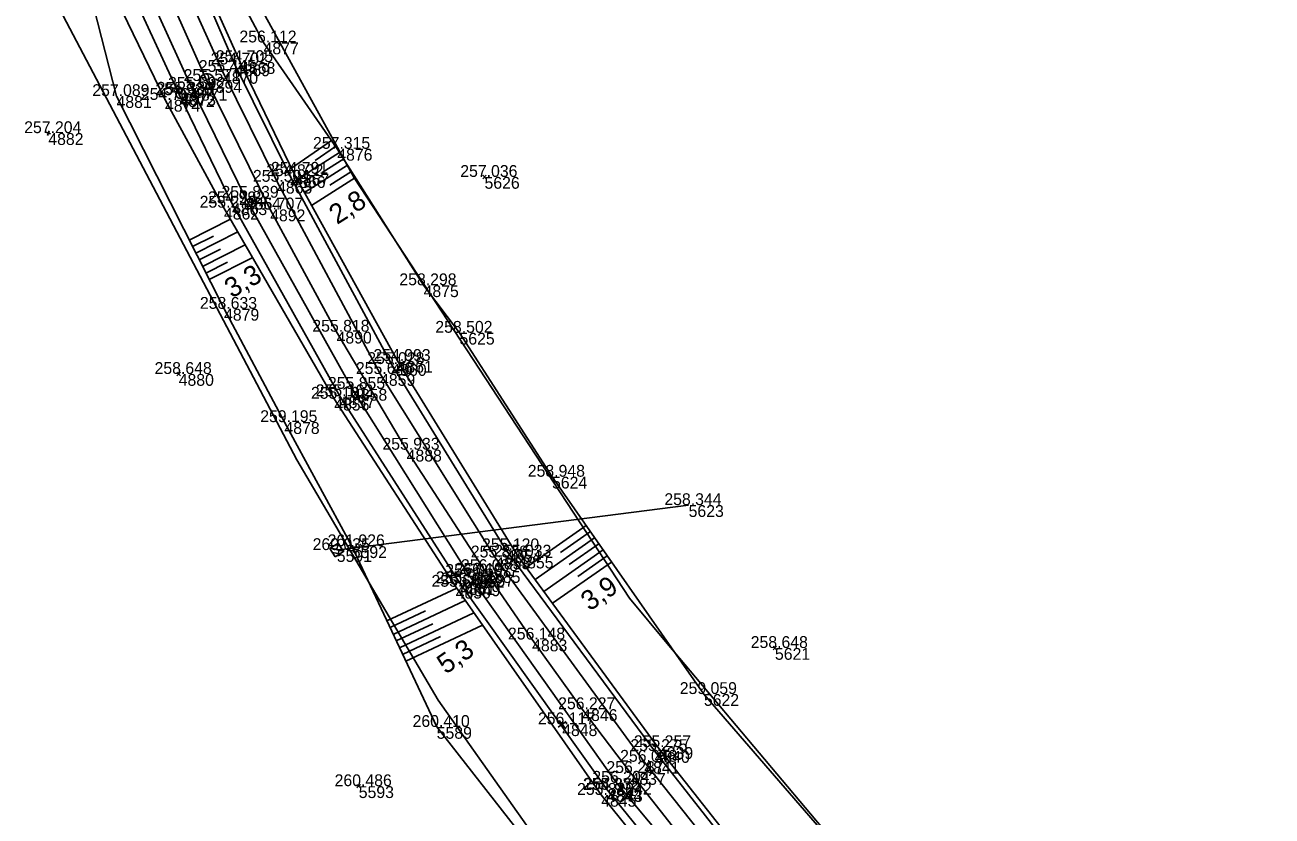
# Model space of a CAD drawing. Extents: x -809970 to -809480, y -1011362 to -1010672.
# Drawn here: x -809838.5 to -809711.9, y -1011112.9 to -1011032.7 of the extents above; entities that cross this region are included whole.
import ezdxf

# ---------------------------------------------------------------- set-up
doc = ezdxf.new("R2010")
doc.units = 0
for name, color, linetype in [('Vrstva 1', 7, 'Continuous'), ('Vrstva 25', 7, 'Continuous'), ('Vrstva 36', 7, 'Continuous'), ('Vrstva 4', 7, 'Continuous'), ('Vrstva 48', 7, 'Continuous'), ('Vrstva 49', 7, 'Continuous'), ('Vrstva 53', 7, 'Continuous'), ('Vrstva 60', 7, 'Continuous'), ('Vrstva 61', 7, 'Continuous'), ('Vrstva 7', 7, 'Continuous')]:
    doc.layers.add(name, color=color, linetype=linetype)

msp = doc.modelspace()

# ---------------------------------------------------------------- linework, layer by layer
at = {"layer": 'Vrstva 1'}
msp.add_lwpolyline([(-809704.48, -1011179.77), (-809716.3, -1011170.61), (-809726.57, -1011161.99), (-809737.88, -1011151.76), (-809747.09, -1011142.76), (-809755.44, -1011134.04), (-809764.34, -1011124.1), (-809767.12, -1011120.83), (-809771.86, -1011115.08), (-809777.01, -1011108.56), (-809781.91, -1011102.09), (-809787, -1011095.02), (-809791.76, -1011088.08), (-809799.73, -1011075.77), (-809806.84, -1011063.8), (-809813.58, -1011051.4), (-809820, -1011038.37), (-809825.44, -1011026.1)], dxfattribs=at)
at = {"layer": 'Vrstva 25'}
msp.add_lwpolyline([(-809806.82, -1011085.95), (-809771.12, -1011081.39)], dxfattribs=at)
at = {"layer": 'Vrstva 36'}
for p, q in [((-809806.19, -1011086), (-809807.41, -1011085.74)), ((-809806.51, -1011086.34), (-809807.26, -1011086.18)), ((-809806.5, -1011085.53), (-809806.94, -1011085.43))]:
    msp.add_line(p, q, dxfattribs=at)
msp.add_lwpolyline([(-809806.97, -1011086.64), (-809807.51, -1011085.8), (-809806.67, -1011085.26), (-809806.13, -1011086.1), (-809806.97, -1011086.64)], dxfattribs=at)
at = {"layer": 'Vrstva 4'}
for points in [[(-809514.07, -1011276.67), (-809539.83, -1011264.26), (-809562.29, -1011253.6), (-809585.06, -1011242.59), (-809604.03, -1011233.74), (-809622.75, -1011224.34), (-809635.98, -1011217.78), (-809658.04, -1011205.96), (-809678.21, -1011194.44), (-809694.3, -1011183.84), (-809703.86, -1011176.66), (-809724.9, -1011159.78), (-809744.11, -1011141.6), (-809762.15, -1011122.16), (-809774.57, -1011106.33), (-809789.63, -1011085.97), (-809801.28, -1011067.08), (-809811.54, -1011048.02), (-809817.16, -1011036.69), (-809823.08, -1011022.98)], [(-809514.73, -1011277.55), (-809539.87, -1011265.31), (-809562.72, -1011254.42), (-809585.31, -1011243.69), (-809604.51, -1011234.26), (-809623.3, -1011225.16), (-809636.52, -1011218.94), (-809659.57, -1011206.8), (-809678.11, -1011195.78), (-809694.14, -1011185.08), (-809704.56, -1011177.6), (-809725.72, -1011160.53), (-809745.22, -1011142.43), (-809763.07, -1011123.23), (-809775.62, -1011107.42), (-809790.76, -1011086.7), (-809802.43, -1011068.09), (-809812.88, -1011048.59), (-809818.37, -1011037.45), (-809824.5, -1011023.86)], [(-809517.34, -1011281.17), (-809542.25, -1011268.91), (-809565.05, -1011257.74), (-809585.85, -1011248.03), (-809606.19, -1011237.96), (-809624.44, -1011229.46), (-809639.03, -1011221.78), (-809662.37, -1011209.59), (-809679.75, -1011199.24), (-809695.35, -1011189.16), (-809706.37, -1011181.63), (-809728.71, -1011163.52), (-809748.04, -1011145.82), (-809766.46, -1011126.18), (-809779.35, -1011110.29), (-809779.4, -1011110.26), (-809794.33, -1011089.31), (-809806.51, -1011070.34), (-809817.46, -1011050.77), (-809822.78, -1011039.81), (-809827.65, -1011029.26)], [(-809516.72, -1011279.86), (-809541.72, -1011267.84), (-809564.36, -1011257.13), (-809585.64, -1011247.05), (-809605.96, -1011237.21), (-809624.35, -1011228.4), (-809638.66, -1011221.38), (-809661.97, -1011208.93), (-809679.17, -1011198.73), (-809694.94, -1011188.71), (-809705.67, -1011180.87), (-809727.9, -1011162.91), (-809747.29, -1011144.85), (-809765.46, -1011125.12), (-809778.44, -1011109.55), (-809793.36, -1011088.57), (-809805.27, -1011069.6), (-809816.07, -1011050.21), (-809821.49, -1011039.16), (-809826.21, -1011028.82)]]:
    msp.add_lwpolyline(points, dxfattribs=at)
at = {"layer": 'Vrstva 48'}
for p, q in [((-809807.36, -1011044.39), (-809811.42, -1011047.21)), ((-809806.53, -1011045.64), (-809810.83, -1011048.36)), ((-809806.94, -1011045.01), (-809809.01, -1011046.45)), ((-809805.72, -1011046.9), (-809810.1, -1011049.67)), ((-809806.12, -1011046.27), (-809808.29, -1011047.64)), ((-809804.92, -1011048.17), (-809809.37, -1011050.99)), ((-809805.32, -1011047.54), (-809807.53, -1011048.94)), ((-809821.79, -1011054.5), (-809817.6, -1011052.38)), ((-809821.45, -1011055.17), (-809819.34, -1011054.1)), ((-809821.12, -1011055.84), (-809816.85, -1011053.68)), ((-809820.78, -1011056.51), (-809818.63, -1011055.42)), ((-809820.44, -1011057.18), (-809816.1, -1011054.98)), ((-809820.1, -1011057.85), (-809817.91, -1011056.74)), ((-809819.76, -1011058.52), (-809815.35, -1011056.29)), ((-809781.52, -1011083.47), (-809787.59, -1011087.72)), ((-809780.66, -1011084.7), (-809786.7, -1011088.93)), ((-809781.08, -1011084.08), (-809784.11, -1011086.2)), ((-809779.8, -1011085.93), (-809785.81, -1011090.14)), ((-809780.23, -1011085.31), (-809783.24, -1011087.42)), ((-809779.37, -1011086.54), (-809782.37, -1011088.64)), ((-809778.94, -1011087.16), (-809784.93, -1011091.35)), ((-809801.73, -1011093.14), (-809794.65, -1011089.81)), ((-809801.09, -1011094.5), (-809793.78, -1011091.05)), ((-809801.41, -1011093.82), (-809797.82, -1011092.12)), ((-809800.46, -1011095.85), (-809792.91, -1011092.3)), ((-809800.78, -1011095.17), (-809797.06, -1011093.43)), ((-809799.82, -1011097.21), (-809792.04, -1011093.55)), ((-809800.14, -1011096.53), (-809796.31, -1011094.73))]:
    msp.add_line(p, q, dxfattribs=at)
at = {"layer": 'Vrstva 49'}
for p, q in [((-809836.01, -1011043.42), (-809836.17, -1011043.89)), ((-809836.33, -1011043.57), (-809835.86, -1011043.74)), ((-809792.01, -1011047.92), (-809791.66, -1011048.28)), ((-809792.01, -1011048.28), (-809791.66, -1011047.92)), ((-809823.04, -1011067.91), (-809822.68, -1011068.27)), ((-809823.04, -1011068.27), (-809822.68, -1011067.91)), ((-809762.54, -1011095.7), (-809762.19, -1011096.06)), ((-809762.54, -1011096.06), (-809762.19, -1011095.7)), ((-809804.77, -1011109.72), (-809804.41, -1011110.08)), ((-809804.77, -1011110.08), (-809804.41, -1011109.72))]:
    msp.add_line(p, q, dxfattribs=at)
for points in [[(-809511.61, -1011271.23), (-809536.39, -1011258.33), (-809560.01, -1011246.27), (-809576.21, -1011238.32), (-809612.21, -1011219.9), (-809615.12, -1011217.12), (-809615.79, -1011215.73), (-809619.54, -1011223.55), (-809624.01, -1011221.32), (-809620.33, -1011213.39), (-809626.47, -1011211.63), (-809636.4, -1011208.19), (-809641.71, -1011205.47), (-809669.15, -1011190.8), (-809699.73, -1011169.4), (-809726.54, -1011146.85), (-809748.5, -1011124.91), (-809769.57, -1011100.55), (-809784.98, -1011078.51), (-809794.37, -1011063.91), (-809798.01, -1011059.09), (-809806.77, -1011045.25), (-809814.25, -1011034.46), (-809820.96, -1011021.87)], [(-809703.94, -1011175.69), (-809724.27, -1011159.21), (-809743.72, -1011141.01), (-809761.9, -1011121.58), (-809774.23, -1011105.94), (-809788.4, -1011086.61), (-809800.65, -1011066.76), (-809811.15, -1011047.78), (-809816.63, -1011036.45), (-809822.75, -1011022.84)], [(-809517.95, -1011282.18), (-809542.49, -1011269.58), (-809565.63, -1011258.32), (-809585.98, -1011248.4), (-809606.44, -1011238.24), (-809621.62, -1011231.05), (-809624.45, -1011230.4), (-809627.73, -1011228.86), (-809639.59, -1011222.81), (-809662.84, -1011211.14), (-809680.58, -1011200.68), (-809695.92, -1011190.37), (-809707.33, -1011182.3), (-809729.57, -1011164.32), (-809748.84, -1011146.41), (-809766.98, -1011126.93), (-809779.99, -1011110.78), (-809794.75, -1011089.67), (-809807.08, -1011070.6), (-809818.27, -1011051.22), (-809824.25, -1011040.29), (-809829.11, -1011030.23)], [(-809702.86, -1011197.5), (-809722.79, -1011182.74), (-809742.35, -1011166.01), (-809762.31, -1011145.88), (-809777.77, -1011128.05), (-809796.68, -1011103.89), (-809805.3, -1011085.56), (-809812.13, -1011072.97), (-809818.26, -1011061.48), (-809829.17, -1011039.9), (-809831.46, -1011030.92)]]:
    msp.add_lwpolyline(points, dxfattribs=at)
at = {"layer": 'Vrstva 53'}
for points in [[(-809817.83, -1011024.91), (-809805.06, -1011048.21), (-809777.13, -1011090.84), (-809773.31, -1011095.41), (-809752.3, -1011120.38), (-809722.41, -1011150.52), (-809685.06, -1011180.11), (-809638.61, -1011207.44), (-809624.45, -1011211.08), (-809620, -1011212.86), (-809615.56, -1011215.28), (-809614.76, -1011215.85), (-809598.39, -1011227.55), (-809488.36, -1011283.38)], [(-809479.96, -1011306.98), (-809541.53, -1011278.39), (-809624.88, -1011241.51), (-809627.72, -1011240.25), (-809632.39, -1011238.49), (-809632.72, -1011238.43), (-809644.97, -1011236.14), (-809685.42, -1011208.04), (-809719.22, -1011184.3), (-809751.99, -1011157.11), (-809779.01, -1011125.97), (-809796.54, -1011101.19), (-809810.89, -1011076.81), (-809836.26, -1011028.53)]]:
    msp.add_lwpolyline(points, dxfattribs=at)
at = {"layer": 'Vrstva 60'}
for p, q in [((-809814.25, -1011034.46), (-809814.25, -1011034.46)), ((-809817.16, -1011036.69), (-809817.16, -1011036.69)), ((-809816.63, -1011036.45), (-809816.63, -1011036.45)), ((-809820, -1011038.37), (-809820, -1011038.37)), ((-809818.37, -1011037.45), (-809818.37, -1011037.45)), ((-809822.65, -1011039.66), (-809822.65, -1011039.66)), ((-809821.49, -1011039.16), (-809821.49, -1011039.16)), ((-809829.17, -1011039.9), (-809829.17, -1011039.9)), ((-809824.25, -1011040.29), (-809824.25, -1011040.29)), ((-809822.78, -1011039.81), (-809822.78, -1011039.81)), ((-809836.09, -1011043.66), (-809836.09, -1011043.66)), ((-809806.77, -1011045.25), (-809806.77, -1011045.25)), ((-809812.88, -1011048.59), (-809812.88, -1011048.59)), ((-809811.54, -1011048.02), (-809811.54, -1011048.02)), ((-809811.15, -1011047.78), (-809811.15, -1011047.78)), ((-809791.83, -1011048.1), (-809791.83, -1011048.1)), ((-809817.46, -1011050.77), (-809817.46, -1011050.77)), ((-809816.07, -1011050.21), (-809816.07, -1011050.21)), ((-809818.27, -1011051.22), (-809818.27, -1011051.22)), ((-809813.58, -1011051.4), (-809813.58, -1011051.4)), ((-809798.01, -1011059.09), (-809798.01, -1011059.09)), ((-809818.26, -1011061.48), (-809818.26, -1011061.48)), ((-809806.84, -1011063.8), (-809806.84, -1011063.8)), ((-809794.37, -1011063.91), (-809794.37, -1011063.91)), ((-809801.28, -1011067.08), (-809801.28, -1011067.08)), ((-809800.65, -1011066.76), (-809800.65, -1011066.76)), ((-809822.86, -1011068.09), (-809822.86, -1011068.09)), ((-809802.43, -1011068.09), (-809802.43, -1011068.09)), ((-809805.27, -1011069.6), (-809805.27, -1011069.6)), ((-809807.08, -1011070.6), (-809807.08, -1011070.6)), ((-809806.51, -1011070.34), (-809806.51, -1011070.34)), ((-809812.13, -1011072.97), (-809812.13, -1011072.97)), ((-809799.73, -1011075.77), (-809799.73, -1011075.77)), ((-809784.98, -1011078.51), (-809784.98, -1011078.51)), ((-809771.12, -1011081.39), (-809771.12, -1011081.39)), ((-809806.82, -1011085.95), (-809806.82, -1011085.95)), ((-809805.3, -1011085.56), (-809805.3, -1011085.56)), ((-809789.63, -1011085.97), (-809789.63, -1011085.97)), ((-809790.76, -1011086.7), (-809790.76, -1011086.7)), ((-809788.4, -1011086.61), (-809788.4, -1011086.61)), ((-809793.36, -1011088.57), (-809793.36, -1011088.57)), ((-809792.42, -1011088.45), (-809792.42, -1011088.45)), ((-809791.76, -1011088.08), (-809791.76, -1011088.08)), ((-809794.75, -1011089.67), (-809794.75, -1011089.67)), ((-809794.33, -1011089.31), (-809794.33, -1011089.31)), ((-809793.79, -1011089.43), (-809793.79, -1011089.43)), ((-809787, -1011095.02), (-809787, -1011095.02)), ((-809762.36, -1011095.88), (-809762.36, -1011095.88)), ((-809769.57, -1011100.55), (-809769.57, -1011100.55)), ((-809781.91, -1011102.09), (-809781.91, -1011102.09)), ((-809796.68, -1011103.89), (-809796.68, -1011103.89)), ((-809783.95, -1011103.62), (-809783.95, -1011103.62)), ((-809774.57, -1011106.33), (-809774.57, -1011106.33)), ((-809774.23, -1011105.94), (-809774.23, -1011105.94)), ((-809775.62, -1011107.42), (-809775.62, -1011107.42)), ((-809777.01, -1011108.56), (-809777.01, -1011108.56)), ((-809804.59, -1011109.9), (-809804.59, -1011109.9)), ((-809779.4, -1011110.26), (-809779.4, -1011110.26)), ((-809779.35, -1011110.29), (-809779.35, -1011110.29)), ((-809778.44, -1011109.55), (-809778.44, -1011109.55)), ((-809779.99, -1011110.78), (-809779.99, -1011110.78))]:
    msp.add_line(p, q, dxfattribs=at)
at = {"layer": 'Vrstva 7'}
for p, q in [((-809822.67, -1011039.61), (-809822.62, -1011039.7)), ((-809793.52, -1011089.85), (-809794.06, -1011089.01)), ((-809794.21, -1011089.7), (-809793.37, -1011089.16)), ((-809784.36, -1011103.92), (-809783.55, -1011103.33)), ((-809783.66, -1011104.03), (-809784.25, -1011103.22))]:
    msp.add_line(p, q, dxfattribs=at)
for centre, radius in [((-809820, -1011038.37), 0.75), ((-809822.65, -1011039.66), 0.5)]:
    msp.add_circle(centre, radius, dxfattribs=at)

# ---------------------------------------------------------------- texts
at = {"layer": 'Vrstva 48'}
for s, rotation, p in [('2,8', 32.3325, (-809806.79, -1011052.98)), ('3,3', 30.0164, (-809817.47, -1011060.45)), ('3,9', 34.972, (-809781.16, -1011092.2)), ('5,3', 34.9592, (-809795.76, -1011098.6))]:
    msp.add_text(s, height=2, rotation=rotation, dxfattribs=at).set_placement(p)
at = {"layer": 'Vrstva 60'}
for s, p in [('4877', (-809814.25, -1011035.66)), ('4869', (-809817.16, -1011037.89)), ('4868', (-809816.63, -1011037.65)), ('4894', (-809820, -1011039.57)), ('4870', (-809818.37, -1011038.65)), ('4873', (-809822.65, -1011040.86)), ('4871', (-809821.49, -1011040.36)), ('4881', (-809829.17, -1011041.1)), ('4874', (-809824.25, -1011041.48)), ('4872', (-809822.78, -1011041.01)), ('4882', (-809836.09, -1011044.86)), ('4876', (-809806.77, -1011046.45)), ('4865', (-809812.88, -1011049.79)), ('4866', (-809811.54, -1011049.22)), ('4867', (-809811.15, -1011048.98)), ('5626', (-809791.83, -1011049.3)), ('4863', (-809817.46, -1011051.97)), ('4864', (-809816.07, -1011051.42)), ('4862', (-809818.27, -1011052.42)), ('4892', (-809813.58, -1011052.6)), ('4875', (-809798.01, -1011060.29)), ('4879', (-809818.26, -1011062.68)), ('4890', (-809806.84, -1011065)), ('5625', (-809794.37, -1011065.11)), ('4860', (-809801.28, -1011068.28)), ('4861', (-809800.65, -1011067.96)), ('4880', (-809822.86, -1011069.29)), ('4859', (-809802.43, -1011069.29)), ('4858', (-809805.27, -1011070.8)), ('4856', (-809807.08, -1011071.8)), ('4857', (-809806.51, -1011071.54)), ('4878', (-809812.13, -1011074.17)), ('4888', (-809799.73, -1011076.97)), ('5624', (-809784.98, -1011079.71)), ('5623', (-809771.12, -1011082.59)), ('5591', (-809806.82, -1011087.15)), ('5592', (-809805.3, -1011086.76)), ('4854', (-809789.63, -1011087.18)), ('4853', (-809790.76, -1011087.9)), ('4855', (-809788.4, -1011087.81)), ('4852', (-809793.36, -1011089.77)), ('4887', (-809792.42, -1011089.65)), ('4885', (-809791.76, -1011089.28)), ('4850', (-809794.75, -1011090.87)), ('4851', (-809794.33, -1011090.51)), ('4849', (-809793.79, -1011090.63)), ('4883', (-809787, -1011096.22)), ('5621', (-809762.36, -1011097.08)), ('5622', (-809769.57, -1011101.75)), ('4846', (-809781.91, -1011103.29)), ('5589', (-809796.68, -1011105.09)), ('4848', (-809783.95, -1011104.82)), ('4840', (-809774.57, -1011107.53)), ('4839', (-809774.23, -1011107.14)), ('4841', (-809775.62, -1011108.62)), ('4837', (-809777.01, -1011109.76)), ('5593', (-809804.59, -1011111.1)), ('4844', (-809779.4, -1011111.46)), ('4843', (-809779.35, -1011111.49)), ('4842', (-809778.44, -1011110.75)), ('4845', (-809779.99, -1011111.98))]:
    msp.add_text(s, height=1.2, dxfattribs=at).set_placement(p)
at = {"layer": 'Vrstva 61'}
for s, p in [('256.112', (-809816.7, -1011034.46)), ('254.702', (-809819.61, -1011036.69)), ('254.705', (-809819.09, -1011036.45)), ('255.571', (-809822.36, -1011038.37)), ('255.445', (-809820.82, -1011037.45)), ('255.389', (-809825.1, -1011039.66)), ('255.592', (-809823.94, -1011039.16)), ('257.089', (-809831.63, -1011039.9)), ('254.764', (-809826.7, -1011040.29)), ('254.936', (-809825.23, -1011039.81)), ('257.204', (-809838.54, -1011043.66)), ('257.315', (-809809.23, -1011045.25)), ('254.822', (-809813.98, -1011048.02)), ('254.791', (-809813.5, -1011047.78)), ('257.036', (-809794.29, -1011048.1)), ('255.504', (-809815.33, -1011048.59)), ('254.992', (-809819.9, -1011050.77)), ('255.839', (-809818.52, -1011050.21)), ('255.249', (-809820.73, -1011051.22)), ('255.707', (-809816.03, -1011051.4)), ('258.298', (-809800.47, -1011059.09)), ('258.633', (-809820.71, -1011061.48)), ('255.818', (-809809.3, -1011063.8)), ('258.502', (-809796.82, -1011063.91)), ('255.028', (-809803.73, -1011067.08)), ('254.993', (-809803.1, -1011066.76)), ('258.648', (-809825.31, -1011068.09)), ('255.646', (-809804.88, -1011068.09)), ('255.855', (-809807.72, -1011069.6)), ('255.161', (-809809.44, -1011070.6)), ('255.162', (-809808.95, -1011070.34)), ('259.195', (-809814.59, -1011072.97)), ('255.933', (-809802.19, -1011075.77)), ('258.948', (-809787.44, -1011078.51)), ('258.344', (-809773.58, -1011081.39)), ('260.035', (-809809.27, -1011085.95)), ('261.926', (-809807.75, -1011085.56)), ('255.120', (-809792.08, -1011085.97)), ('255.878', (-809793.22, -1011086.7)), ('255.033', (-809790.85, -1011086.61)), ('256.060', (-809795.81, -1011088.57)), ('256.197', (-809794.87, -1011088.45)), ('256.088', (-809794.22, -1011088.08)), ('255.585', (-809797.21, -1011089.67)), ('255.542', (-809796.77, -1011089.31)), ('255.930', (-809796.24, -1011089.43)), ('256.148', (-809789.45, -1011095.02)), ('258.648', (-809764.82, -1011095.88)), ('259.059', (-809772.02, -1011100.55)), ('256.227', (-809784.36, -1011102.09)), ('260.410', (-809799.13, -1011103.89)), ('256.117', (-809786.41, -1011103.62)), ('255.275', (-809777.03, -1011106.33)), ('255.257', (-809776.68, -1011105.94)), ('256.048', (-809778.07, -1011107.42)), ('256.287', (-809779.46, -1011108.56)), ('260.486', (-809807.04, -1011109.9)), ('255.832', (-809781.84, -1011110.26)), ('254.875', (-809781.8, -1011110.29)), ('256.204', (-809780.89, -1011109.55)), ('255.822', (-809782.44, -1011110.78))]:
    msp.add_text(s, height=1.2, dxfattribs=at).set_placement(p)

doc.saveas('drawing.dxf')
